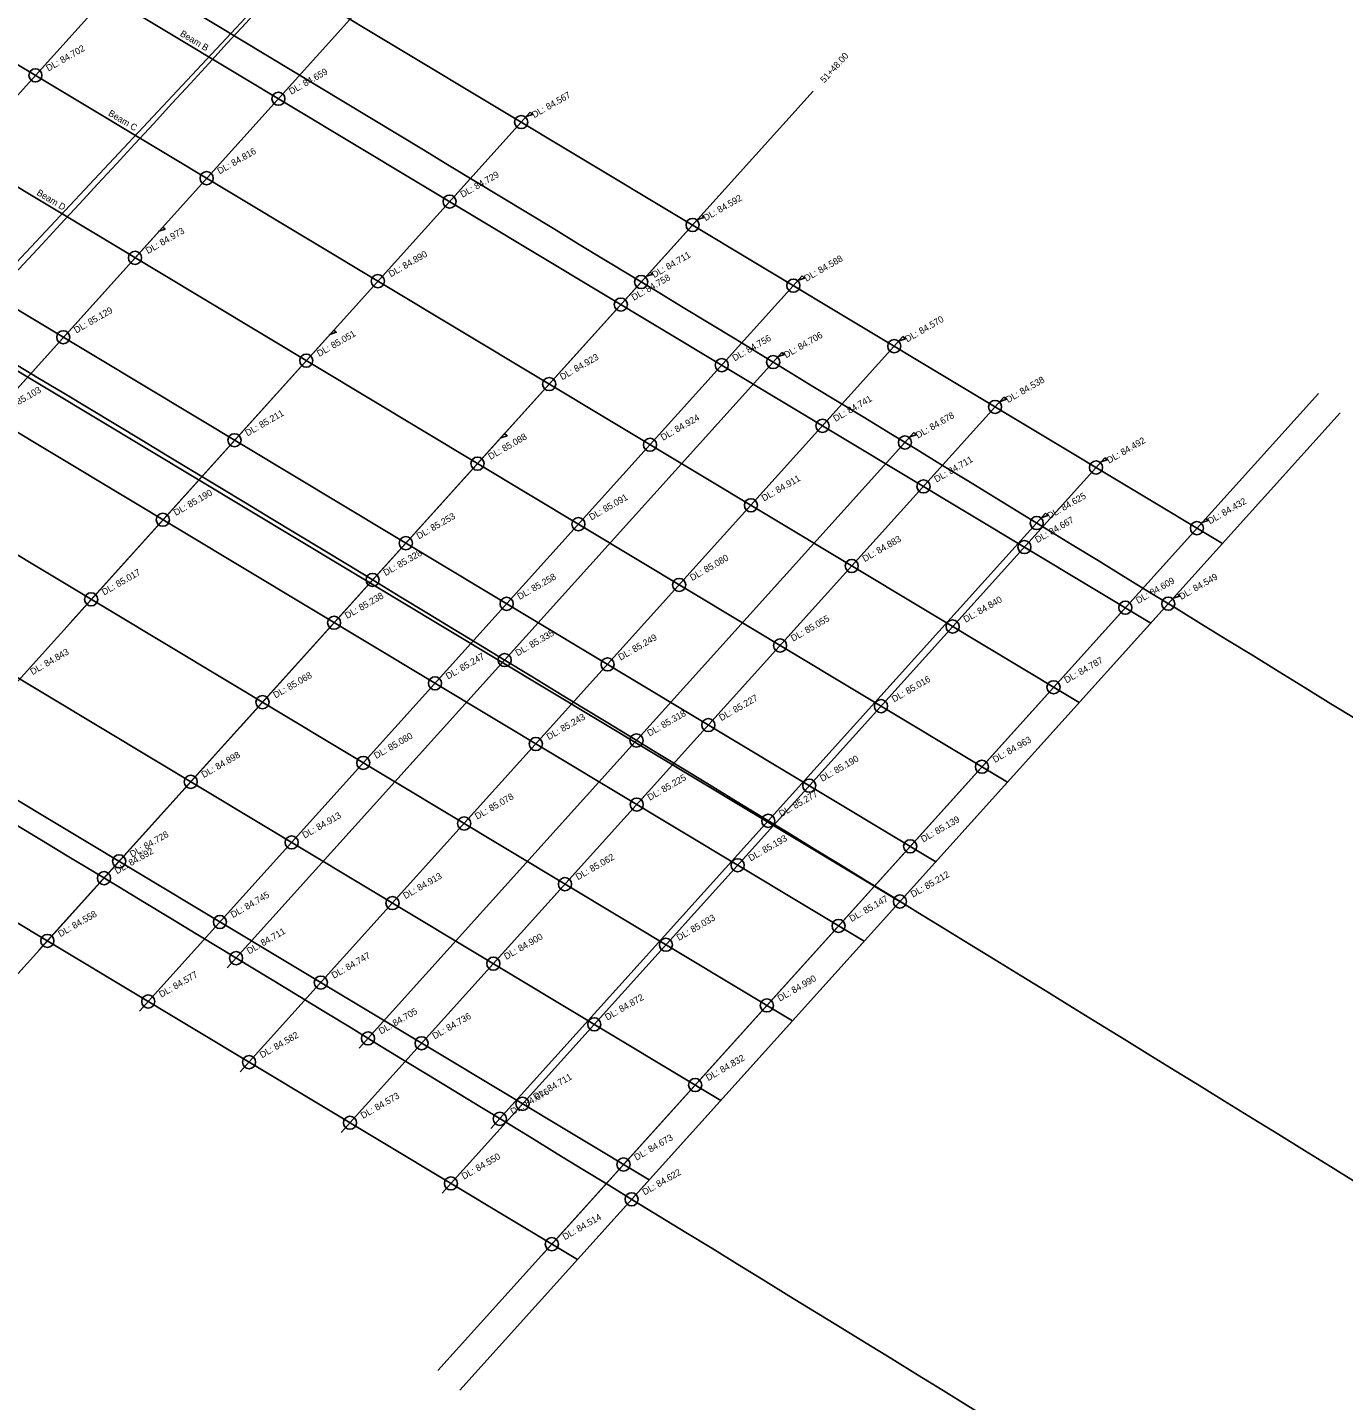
# Model space of a CAD drawing. Extents: x 3599070 to 3599898, y 342469 to 342989.
# Drawn here: x 3599620.3 to 3599720.4, y 342578.7 to 342683.2 of the extents above; entities that cross this region are included whole.
import ezdxf

# ---------------------------------------------------------------- set-up
doc = ezdxf.new("R2010")
doc.units = 0
for name, color, linetype in [('B', 7, 'Continuous'), ('EE', 7, 'Continuous'), ('GUARDRAIL', 7, 'Continuous'), ('PROLINE', 7, 'Continuous'), ('TOE', 7, 'Continuous')]:
    doc.layers.add(name, color=color, linetype=linetype)

msp = doc.modelspace()

# ---------------------------------------------------------------- linework, layer by layer
at = {"layer": 'B'}
for p, q in [((3599565.51, 342731.51), (3599711.21, 342643.92)), ((3599560.06, 342725.46), (3599705.75, 342637.87)), ((3599554.6, 342719.4), (3599700.3, 342631.81)), ((3599549.15, 342713.35), (3599694.84, 342625.76)), ((3599543.69, 342707.29), (3599689.39, 342619.7)), ((3599538.24, 342701.24), (3599683.93, 342613.64)), ((3599532.78, 342695.18), (3599678.48, 342607.59)), ((3599527.33, 342689.13), (3599673.02, 342601.53)), ((3599521.87, 342683.07), (3599667.57, 342595.48)), ((3599680.06, 342678.36), (3599613, 342603.92)), ((3599516.42, 342677.02), (3599662.11, 342589.42)), ((3599718.5, 342655.35), (3599651.5, 342580.97))]:
    msp.add_line(p, q, dxfattribs=at)
at = {"layer": 'EE'}
for points in [[(3599632.45, 342692.41), (3599582.02, 342636.43)], [(3599645.48, 342684.58), (3599595.05, 342628.6)], [(3599658.51, 342676.75), (3599608.08, 342620.76)], [(3599658.22, 342676.42), (3599658.7, 342676.58), (3599658.51, 342676.75)], [(3599671.55, 342668.91), (3599621.11, 342612.93)], [(3599671.26, 342668.59), (3599671.73, 342668.74), (3599671.55, 342668.91)], [(3599630.56, 342668.01), (3599610.48, 342645.73)], [(3599630.27, 342667.69), (3599630.74, 342667.85), (3599630.56, 342668.01)], [(3599667.64, 342664.58), (3599625.42, 342617.71)], [(3599667.35, 342664.26), (3599667.83, 342664.41), (3599667.64, 342664.58)], [(3599679.22, 342664.3), (3599628.79, 342608.31)], [(3599678.93, 342663.97), (3599679.4, 342664.13), (3599679.22, 342664.3)], [(3599643.57, 342660.16), (3599623.49, 342637.87)], [(3599643.28, 342659.84), (3599643.76, 342660), (3599643.57, 342660.16)], [(3599686.89, 342659.68), (3599636.46, 342603.7)], [(3599686.61, 342659.36), (3599687.08, 342659.51), (3599686.89, 342659.68)], [(3599677.68, 342658.47), (3599635.47, 342611.62)], [(3599677.39, 342658.15), (3599677.87, 342658.31), (3599677.68, 342658.47)], [(3599694.57, 342655.07), (3599644.14, 342599.08)], [(3599694.28, 342654.74), (3599694.76, 342654.9), (3599694.57, 342655.07)], [(3599656.57, 342652.29), (3599636.49, 342630)], [(3599687.71, 342652.36), (3599645.51, 342605.51)], [(3599656.28, 342651.97), (3599656.76, 342652.12), (3599656.57, 342652.29)], [(3599687.42, 342652.03), (3599687.9, 342652.19), (3599687.71, 342652.36)], [(3599702.25, 342650.45), (3599651.82, 342594.47)], [(3599701.96, 342650.13), (3599702.44, 342650.28), (3599702.25, 342650.45)], [(3599697.73, 342646.23), (3599655.54, 342599.39)], [(3599709.93, 342645.83), (3599659.5, 342589.85)], [(3599697.45, 342645.9), (3599697.92, 342646.06), (3599697.73, 342646.23)], [(3599709.64, 342645.51), (3599710.11, 342645.67), (3599709.93, 342645.83)], [(3599707.75, 342640.08), (3599665.57, 342593.26)], [(3599707.46, 342639.76), (3599707.94, 342639.92), (3599707.75, 342640.08)]]:
    msp.add_lwpolyline(points, dxfattribs=at)
for centre in [(3599620.87, 342679.56), (3599639.36, 342677.78), (3599657.84, 342676), (3599633.9, 342671.73), (3599652.39, 342669.95), (3599670.88, 342668.17), (3599628.45, 342665.67), (3599646.93, 342663.89), (3599666.97, 342663.83), (3599678.55, 342663.55), (3599665.42, 342662.11), (3599622.99, 342659.62), (3599686.23, 342658.94), (3599641.48, 342657.84), (3599677.01, 342657.73), (3599673.1, 342657.5), (3599659.97, 342656.06), (3599693.9, 342654.32), (3599680.77, 342652.88), (3599636.02, 342651.78), (3599667.64, 342651.44), (3599687.04, 342651.61), (3599654.51, 342650), (3599701.58, 342649.71), (3599688.45, 342648.27), (3599675.32, 342646.83), (3599630.57, 342645.73), (3599662.19, 342645.39), (3599697.07, 342645.48), (3599709.26, 342645.09), (3599649.06, 342643.95), (3599696.13, 342643.65), (3599682.99, 342642.21), (3599646.53, 342641.15), (3599669.86, 342640.77), (3599625.11, 342639.67), (3599656.73, 342639.33), (3599703.81, 342639.04), (3599707.08, 342639.34), (3599643.6, 342637.89), (3599690.67, 342637.6), (3599677.54, 342636.16), (3599656.58, 342635.05), (3599664.41, 342634.72), (3599651.28, 342633.28), (3599698.35, 342632.98), (3599638.15, 342631.84), (3599685.22, 342631.54), (3599672.08, 342630.1), (3599658.95, 342628.66), (3599666.61, 342628.93), (3599645.82, 342627.22), (3599692.9, 342626.93), (3599632.69, 342625.78), (3599679.76, 342625.49), (3599666.63, 342624.05), (3599653.5, 342622.61), (3599676.64, 342622.81), (3599640.37, 342621.17), (3599687.44, 342620.87), (3599627.24, 342619.73), (3599674.31, 342619.43), (3599626.09, 342618.45), (3599661.17, 342617.99), (3599648.04, 342616.55), (3599686.66, 342616.67), (3599634.91, 342615.11), (3599681.99, 342614.81), (3599621.78, 342613.67), (3599668.85, 342613.38), (3599636.14, 342612.36), (3599655.72, 342611.94), (3599642.59, 342610.5), (3599629.46, 342609.06), (3599676.53, 342608.76), (3599663.4, 342607.32), (3599646.18, 342606.25), (3599650.26, 342605.88), (3599637.13, 342604.44), (3599671.08, 342602.7), (3599657.94, 342601.27), (3599656.21, 342600.13), (3599644.81, 342599.83), (3599665.62, 342596.65), (3599652.49, 342595.21), (3599666.24, 342594), (3599660.17, 342590.59)]:
    msp.add_circle(centre, 0.499, dxfattribs=at)
at = {"layer": 'GUARDRAIL'}
for p, q in [((3599540.96, 342704.26), (3599686.66, 342616.67)), ((3599680.06, 342678.36), (3599613, 342603.92)), ((3599720.16, 342653.86), (3599653.16, 342579.48))]:
    msp.add_line(p, q, dxfattribs=at)
for centre, radius, start, end in [((3597781.98, 344376.76), 2511.5, 317.27688, 323.34945), ((3597781.98, 344376.76), 2511.5, 317.27688, 323.34945), ((3597781.98, 344376.76), 2511.5, 317.27688, 323.34945), ((3597781.98, 344376.76), 2511.5, 317.27688, 323.34945), ((3597781.98, 344376.76), 2511.5, 317.27688, 323.34945), ((3597781.98, 344376.76), 2511.5, 317.27688, 323.34945), ((3597781.98, 344376.76), 2511.5, 317.27688, 323.34945), ((3597781.98, 344376.76), 2511.5, 317.27688, 323.34945), ((3597781.98, 344376.76), 2511.5, 317.27688, 323.34945), ((3597781.98, 344376.76), 2511.5, 317.27688, 323.34945), ((3594639.68, 334386.71), 9684.24, 58.937083, 60.687623), ((3594639.68, 334386.71), 9654.24, 58.937083, 60.687778), ((3594650.02, 334403.3), 9664.69, 57.184618, 58.938854), ((3597781.98, 344376.76), 2511.5, 311.2043, 317.27688), ((3597781.98, 344376.76), 2511.5, 311.2043, 317.27688), ((3597781.98, 344376.76), 2511.5, 311.2043, 317.27688), ((3597781.98, 344376.76), 2511.5, 311.2043, 317.27688), ((3597781.98, 344376.76), 2511.5, 311.2043, 317.27688), ((3597781.98, 344376.76), 2511.5, 311.2043, 317.27688), ((3597781.98, 344376.76), 2511.5, 311.2043, 317.27688), ((3597781.98, 344376.76), 2511.5, 311.2043, 317.27688), ((3597781.98, 344376.76), 2511.5, 311.2043, 317.27688), ((3597781.98, 344376.76), 2511.5, 311.2043, 317.27688), ((3594639.68, 334386.71), 9654.24, 57.186389, 58.937083), ((3594639.68, 334386.71), 9624.24, 57.186389, 58.937083)]:
    msp.add_arc(centre, radius, start, end, dxfattribs=at)
at = {"layer": 'PROLINE'}
msp.add_line((3599643.56, 342691.1), (3599574.7, 342617.56), dxfattribs=at)

# ---------------------------------------------------------------- texts
at = {"layer": 'B'}
for s, p in [('Beam B', (3599631.83, 342682.6)), ('Beam C', (3599626.37, 342676.54)), ('Beam D', (3599620.92, 342670.49))]:
    msp.add_text(s, height=0.499, rotation=328.986, dxfattribs=at).set_placement(p)
at = {"layer": 'EE'}
for s, p in [('DL: 84.702', (3599621.86, 342679.84)), ('DL: 84.659', (3599640.34, 342678.07)), ('DL: 84.567', (3599658.83, 342676.29)), ('DL: 84.816', (3599634.89, 342672.01)), ('DL: 84.729', (3599653.38, 342670.23)), ('DL: 84.592', (3599671.87, 342668.45)), ('DL: 84.973', (3599629.44, 342665.95)), ('DL: 84.890', (3599647.92, 342664.18)), ('DL: 84.711', (3599667.96, 342664.12)), ('DL: 84.588', (3599679.54, 342663.84)), ('DL: 84.758', (3599666.41, 342662.39)), ('DL: 85.129', (3599623.98, 342659.9)), ('DL: 84.570', (3599687.22, 342659.22)), ('DL: 85.051', (3599642.47, 342658.12)), ('DL: 84.756', (3599674.08, 342657.78)), ('DL: 84.706', (3599678, 342658.01)), ('DL: 84.923', (3599660.96, 342656.34)), ('DL: 84.538', (3599694.89, 342654.61)), ('DL: 85.103', (3599618.53, 342653.84)), ('DL: 84.741', (3599681.76, 342653.17)), ('DL: 85.211', (3599637.01, 342652.07)), ('DL: 84.678', (3599688.03, 342651.9)), ('DL: 84.924', (3599668.63, 342651.73)), ('DL: 85.088', (3599655.5, 342650.28)), ('DL: 84.492', (3599702.57, 342649.99)), ('DL: 84.711', (3599689.44, 342648.55)), ('DL: 84.911', (3599676.31, 342647.11)), ('DL: 85.190', (3599631.56, 342646.01)), ('DL: 85.091', (3599663.18, 342645.67)), ('DL: 84.625', (3599698.05, 342645.77)), ('DL: 84.432', (3599710.25, 342645.37)), ('DL: 85.253', (3599650.05, 342644.23)), ('DL: 84.667', (3599697.12, 342643.94)), ('DL: 84.883', (3599683.98, 342642.5)), ('DL: 85.328', (3599647.52, 342641.43)), ('DL: 85.080', (3599670.85, 342641.06)), ('DL: 85.017', (3599626.1, 342639.96)), ('DL: 85.258', (3599657.72, 342639.62)), ('DL: 84.609', (3599704.79, 342639.32)), ('DL: 84.549', (3599708.07, 342639.62)), ('DL: 85.238', (3599644.59, 342638.17)), ('DL: 84.840', (3599691.66, 342637.88)), ('DL: 85.055', (3599678.53, 342636.44)), ('DL: 85.335', (3599657.57, 342635.33)), ('DL: 85.249', (3599665.4, 342635)), ('DL: 84.843', (3599620.65, 342633.9)), ('DL: 85.247', (3599652.27, 342633.56)), ('DL: 84.787', (3599699.34, 342633.26)), ('DL: 85.068', (3599639.14, 342632.12)), ('DL: 85.016', (3599686.21, 342631.82)), ('DL: 85.227', (3599673.07, 342630.39)), ('DL: 85.243', (3599659.94, 342628.95)), ('DL: 85.318', (3599667.6, 342629.22)), ('DL: 85.080', (3599646.81, 342627.51)), ('DL: 84.963', (3599693.89, 342627.21)), ('DL: 84.898', (3599633.68, 342626.06)), ('DL: 85.190', (3599680.75, 342625.77)), ('DL: 85.225', (3599667.62, 342624.33)), ('DL: 85.078', (3599654.49, 342622.89)), ('DL: 85.277', (3599677.63, 342623.09)), ('DL: 84.913', (3599641.36, 342621.45)), ('DL: 85.139', (3599688.43, 342621.15)), ('DL: 84.728', (3599628.23, 342620.01)), ('DL: 85.193', (3599675.3, 342619.71)), ('DL: 84.692', (3599627.08, 342618.74)), ('DL: 85.062', (3599662.16, 342618.28)), ('DL: 84.913', (3599649.03, 342616.84)), ('DL: 85.212', (3599687.65, 342616.96)), ('DL: 84.745', (3599635.9, 342615.4)), ('DL: 85.147', (3599682.98, 342615.1)), ('DL: 84.558', (3599622.77, 342613.95)), ('DL: 85.033', (3599669.84, 342613.66)), ('DL: 84.711', (3599637.13, 342612.64)), ('DL: 84.900', (3599656.71, 342612.22)), ('DL: 84.747', (3599643.58, 342610.78)), ('DL: 84.577', (3599630.45, 342609.34)), ('DL: 84.990', (3599677.52, 342609.04)), ('DL: 84.872', (3599664.39, 342607.6)), ('DL: 84.705', (3599647.17, 342606.54)), ('DL: 84.736', (3599651.25, 342606.17)), ('DL: 84.582', (3599638.12, 342604.73)), ('DL: 84.832', (3599672.07, 342602.99)), ('DL: 84.711', (3599658.93, 342601.55)), ('DL: 84.573', (3599645.8, 342600.11)), ('DL: 84.676', (3599657.2, 342600.42)), ('DL: 84.673', (3599666.61, 342596.93)), ('DL: 84.550', (3599653.48, 342595.49)), ('DL: 84.622', (3599667.23, 342594.29)), ('DL: 84.514', (3599661.16, 342590.88))]:
    msp.add_text(s, height=0.499, rotation=30, dxfattribs=at).set_placement(p)
at = {"layer": 'TOE'}
msp.add_text('51+48.00', height=0.499, rotation=47.9859, dxfattribs=at).set_placement((3599680.91, 342678.94))

doc.saveas('drawing.dxf')
